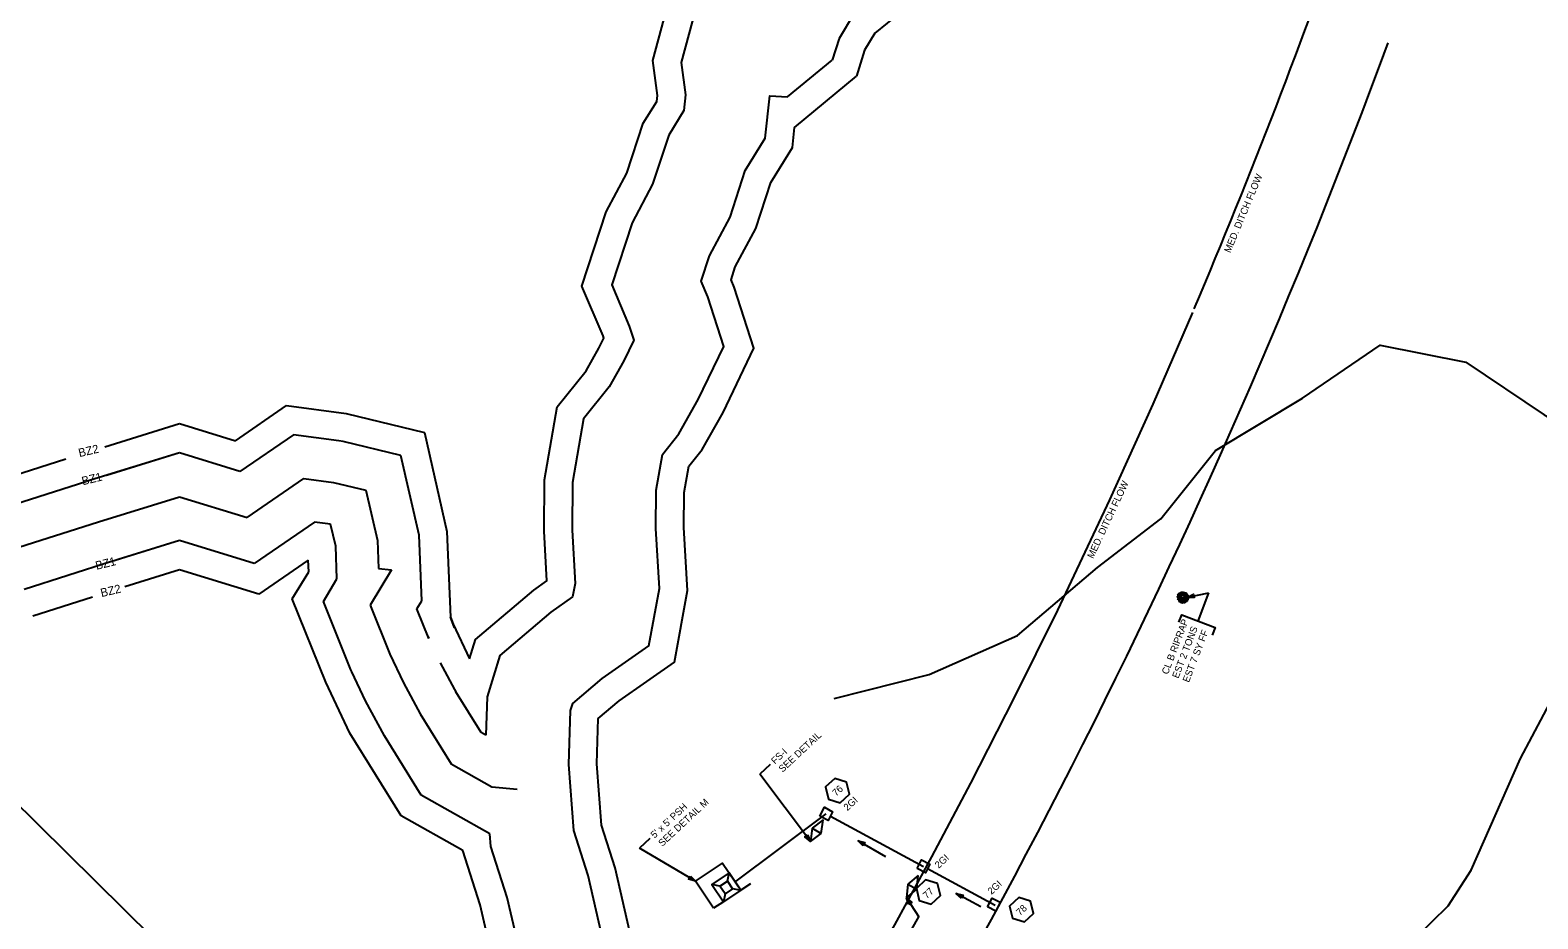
# Model space of a CAD drawing. Extents: x 2384780 to 2405432, y 547869 to 573706.
# Drawn here: x 2399231 to 2400310, y 561684 to 562319 of the extents above; entities that cross this region are included whole.
import ezdxf

# ---------------------------------------------------------------- set-up
doc = ezdxf.new("R2010")
doc.units = 0
for name, color, linetype in [('Default', 7, 'Continuous'), ('Old_Level_1', 7, 'Continuous'), ('Old_Level_19', 7, 'Continuous'), ('Old_Level_20', 7, 'Continuous'), ('Old_Level_5', 7, 'Continuous'), ('Old_Level_6', 7, 'Continuous'), ('Old_Level_62', 7, 'Continuous'), ('Old_Level_63', 7, 'Continuous'), ('Old_Level_9', 7, 'Continuous'), ('Prop Buffer Zone 1', 7, 'Continuous'), ('Prop Buffer Zone 2', 7, 'Continuous'), ('Prop Drainage Box Number Symbol CELL', 7, 'Continuous')]:
    doc.layers.add(name, color=color, linetype=linetype)

msp = doc.modelspace()

# ---------------------------------------------------------------- linework, layer by layer
at = {"layer": 'Default'}
msp.add_arc((2395689.3, 563976), 4811, 326.2779, 339.7425, dxfattribs=at)
at = {"layer": 'Old_Level_1'}
for p, q in [((2399760.5, 561794.1), (2399753.1, 561787.2)), ((2399789.3, 561739), (2399753.1, 561787.2)), ((2399735.2, 561709.8), (2399800.5, 561758.9)), ((2399803.6, 561757.2), (2399870.2, 561721.1)), ((2399674.3, 561741.1), (2399667, 561734.3)), ((2399707.1, 561710.7), (2399667, 561734.3)), ((2399730, 561710.7), (2399731.2, 561716.5)), ((2399873.2, 561719.6), (2399921.5, 561693.5)), ((2399724.5, 561707.1), (2399718.8, 561708.3)), ((2399728.2, 561701.6), (2399727, 561695.9)), ((2399733.6, 561705.3), (2399739.4, 561704.1)), ((2399746.4, 561708.7), (2399739.4, 561704.1)), ((2399858, 561698.8), (2399866.9, 561685)), ((2399727, 561695.9), (2399720, 561691.2)), ((2399861.9, 561676.4), (2399866.9, 561685))]:
    msp.add_line(p, q, dxfattribs=at)
for points in [[(2399796, 561757.2), (2399799.3, 561763.5), (2399805.2, 561760.3), (2399802, 561754.1)], [(2399787.3, 561743.8), (2399789.3, 561739), (2399785.3, 561742.3)], [(2399703.4, 561714.2), (2399707.1, 561710.7), (2399702.1, 561712.1)], [(2399728.2, 561701.6), (2399724.5, 561707.1), (2399730, 561710.7), (2399733.6, 561705.2)], [(2399859.7, 561693.9), (2399858, 561698.8), (2399861.8, 561695.3)]]:
    msp.add_lwpolyline(points, close=True, dxfattribs=at)
for points in [[(2399720, 561691.2), (2399707.1, 561710.7), (2399726.5, 561723.5), (2399739.4, 561704.1)], [(2399739.4, 561704.1), (2399731.2, 561716.5), (2399718.8, 561708.3), (2399727, 561695.9)], [(2399739.4, 561704.1), (2399727, 561695.9)]]:
    msp.add_lwpolyline(points, dxfattribs=at)
for centre, radius in [((2400052.3, 561914.1), 0.298), ((2400052.7, 561915.6), 0.385), ((2400052.8, 561914.7), 0.385), ((2400053.9, 561913.9), 0.854), ((2400053.4, 561916.3), 0.385), ((2400053.6, 561915.5), 0.385), ((2400054.3, 561916.8), 0.385), ((2400054.6, 561915.2), 0.55), ((2400054.7, 561916.1), 0.298), ((2400055.3, 561916.9), 0.55), ((2400055.9, 561914.1), 1.02), ((2400055.5, 561915.7), 0.4), ((2400056.2, 561916.3), 0.298), ((2400056.3, 561917), 0.298), ((2400056.4, 561915.6), 0.298), ((2400057.1, 561916.6), 0.55), ((2400057.3, 561915.4), 0.55), ((2400057.7, 561914.1), 0.718), ((2400058.1, 561916.4), 0.385), ((2400058.5, 561915.4), 0.55), ((2400059.3, 561914.7), 0.385), ((2400052.6, 561913.4), 0.298), ((2400052.8, 561912.5), 0.55), ((2400053.5, 561911.7), 0.298), ((2400053.8, 561910.9), 0.55), ((2400053.8, 561912.6), 0.298), ((2400054.2, 561912), 0.298), ((2400054.8, 561912.7), 0.55), ((2400054.7, 561910.2), 0.385), ((2400055, 561911.2), 0.55), ((2400055.7, 561910), 0.55), ((2400056.1, 561912.2), 0.718), ((2400056.2, 561910.9), 0.298), ((2400057, 561910.3), 0.55), ((2400057.4, 561912.7), 0.55), ((2400057.5, 561911.6), 0.55), ((2400057.8, 561910.7), 0.298), ((2400058.6, 561911.2), 0.55), ((2400058.4, 561913.2), 0.298), ((2400058.4, 561912.5), 0.298), ((2400058.8, 561914), 0.298), ((2400059, 561912.1), 0.385), ((2400059.3, 561913.2), 0.55)]:
    msp.add_circle(centre, radius, dxfattribs=at)
at = {"layer": 'Old_Level_19'}
for points in [[(2400062.7, 562117.3), (2400034.3, 562051.9), (2400003.4, 561983.5), (2399966, 561904.4), (2399935.2, 561841.9)], [(2399935.2, 561841.9), (2399903.8, 561780.7), (2399876, 561728.1), (2399849.4, 561679.3), (2399802.5, 561596.2), (2399773.7, 561547.1), (2399724, 561465.4), (2399672.9, 561385.1), (2399604.3, 561282.6), (2399518.3, 561161.7)]]:
    msp.add_lwpolyline(points, dxfattribs=at)
msp.add_arc((2395691.9, 563975.6), 4749.5, 337.002, 344.5278, dxfattribs=at)
at = {"layer": 'Old_Level_20'}
for p in [(2400059.4, 561913.8), (2400066.7, 561896.7)]:
    msp.add_line(p, (2400074.5, 561916.9), dxfattribs=at)
msp.add_lwpolyline([(2400064, 561913.4), (2400058.9, 561913.5), (2400063.4, 561915.9)], close=True, dxfattribs=at)
msp.add_lwpolyline([(2400053, 561895.8), (2400055, 561901.2), (2400078.9, 561892), (2400076.8, 561886.7)], dxfattribs=at)
at = {"layer": 'Old_Level_5'}
for p, q in [((2399843.3, 561728), (2399823.4, 561739.6)), ((2399911.2, 561692.2), (2399893.7, 561701.9))]:
    msp.add_line(p, q, dxfattribs=at)
for points in [[(2399827.1, 561736), (2399823.4, 561739.6), (2399828.3, 561738.2)], [(2399897.5, 561698.4), (2399893.7, 561701.9), (2399898.7, 561700.6)]]:
    msp.add_lwpolyline(points, close=True, dxfattribs=at)
at = {"layer": 'Old_Level_6'}
for p, q in [((2399386.2, 561970.8), (2399426.9, 561998.7)), ((2399426.9, 561998.7), (2399448, 561995.9)), ((2399448, 561995.9), (2399471.2, 561990.3)), ((2399471.2, 561990.3), (2399479.5, 561954.2)), ((2399279.9, 561967.7), (2399337.8, 561985.6)), ((2399337.8, 561985.6), (2399386.2, 561970.8)), ((2399217.7, 561947.8), (2399279.9, 561967.7)), ((2399479.5, 561954.2), (2399480.3, 561934.2)), ((2399489.5, 561933.3), (2399474.2, 561908.1)), ((2399480.3, 561934.2), (2399489.5, 561933.3)), ((2399474.2, 561908.1), (2399488.4, 561873.1)), ((2399488.4, 561873.1), (2399498.1, 561852.4)), ((2399498.1, 561852.4), (2399510.1, 561830.3)), ((2399510.1, 561830.3), (2399532.2, 561794.6)), ((2399532.2, 561794.6), (2399561.3, 561778.2)), ((2399561.3, 561778.2), (2399579.4, 561776.4))]:
    msp.add_line(p, q, dxfattribs=at)
at = {"layer": 'Old_Level_62'}
for points in [[(2399821.1, 561435.1), (2399926.6, 561478.8), (2399983.8, 561509.2), (2400100, 561551), (2400122.9, 561580.9), (2400187.2, 561635.8), (2400245.6, 561693), (2400262.2, 561718.5), (2400297.4, 561798.3), (2400322.4, 561845.6), (2400375.3, 561929.9), (2400350.2, 561971.4), (2400342.7, 562028.9), (2400380.5, 562062.2), (2400432.1, 562042.4), (2400480, 562001.2), (2400538.6, 562017.4), (2400592.9, 562087.6), (2400691.4, 562124.8), (2400752.6, 562153.7), (2400786.1, 562181.7), (2400835.1, 562178.9), (2400922.9, 562247.5), (2401014.1, 562330.8)], [(2399806.2, 561841.2), (2399874.3, 561858.4), (2399937.4, 561886.4), (2399994.7, 561935), (2400040, 561969.9), (2400079.2, 562018.6), (2400141.4, 562056.1), (2400196.9, 562094), (2400258.3, 562081.8), (2400314.4, 562044.3), (2400342.7, 562028.9)]]:
    msp.add_lwpolyline(points, dxfattribs=at)
at = {"layer": 'Old_Level_63'}
msp.add_lwpolyline([(2399645.6, 561347.3), (2398726.2, 562255.3), (2398336.6, 562216.2)], dxfattribs=at)
at = {"layer": 'Old_Level_9'}
for p, q in [((2399798.5, 561754.4), (2399790.6, 561748.6)), ((2399797, 561744.8), (2399798.5, 561754.4)), ((2399790.6, 561748.6), (2399789.3, 561739)), ((2399789.3, 561739), (2399797, 561744.8)), ((2399790.6, 561748.6), (2399797, 561744.8)), ((2399866.5, 561714.6), (2399858.9, 561708.4)), ((2399865.4, 561704.9), (2399866.5, 561714.6)), ((2399858.9, 561708.4), (2399858, 561698.8)), ((2399858, 561698.8), (2399865.4, 561704.9)), ((2399858.9, 561708.4), (2399865.4, 561704.9))]:
    msp.add_line(p, q, dxfattribs=at)
for points in [[(2399865.6, 561719.6), (2399868.8, 561725.8), (2399874.8, 561722.7), (2399871.6, 561716.5)], [(2399916, 561692.3), (2399919.3, 561698.5), (2399925.2, 561695.5), (2399922, 561689.2)]]:
    msp.add_lwpolyline(points, close=True, dxfattribs=at)
at = {"layer": 'Prop Buffer Zone 1'}
for p, q in [((2399419.4, 562030), (2399381.1, 562003.7)), ((2399451.9, 562025.7), (2399419.4, 562030)), ((2399455, 562025.1), (2399451.9, 562025.7)), ((2399496.3, 562015.1), (2399455, 562025.1)), ((2399496.3, 562015.1), (2399455, 562025.1)), ((2399337.8, 562017), (2399271.1, 561996.4)), ((2399337.8, 562017), (2399285.6, 562000.9)), ((2399381.1, 562003.7), (2399337.8, 562017)), ((2399509.3, 561958.2), (2399496.3, 562015.1)), ((2399509.3, 561958.2), (2399496.3, 562015.1)), ((2399270.8, 561996.3), (2399208.6, 561976.4)), ((2399434.4, 561967.5), (2399391.3, 561937.9)), ((2399434.4, 561967.5), (2399391.3, 561937.9)), ((2399446, 561965.9), (2399434.4, 561967.5)), ((2399446, 561965.9), (2399434.4, 561967.5)), ((2399449.6, 561950.2), (2399446, 561965.9)), ((2399449.6, 561950.2), (2399446, 561965.9)), ((2399511.2, 561911.1), (2399509.3, 561958.2)), ((2399511.2, 561911.1), (2399509.3, 561958.2)), ((2399337.9, 561954.2), (2399288.8, 561939.1)), ((2399337.9, 561954.2), (2399294, 561940.7)), ((2399391.3, 561937.9), (2399337.9, 561954.2)), ((2399391.3, 561937.9), (2399337.9, 561954.2)), ((2399450.5, 561926.8), (2399449.6, 561950.2)), ((2399450.5, 561926.8), (2399449.6, 561950.2)), ((2399289.1, 561939.2), (2399226.8, 561919.3)), ((2399440.8, 561910.7), (2399450.5, 561926.8)), ((2399440.8, 561910.7), (2399450.5, 561926.8)), ((2399460.5, 561861.9), (2399440.8, 561910.7)), ((2399460.5, 561861.9), (2399440.8, 561910.7)), ((2399507.7, 561905.4), (2399511.2, 561911.1)), ((2399507.7, 561905.4), (2399511.2, 561911.1)), ((2399516.2, 561884.3), (2399507.7, 561905.4)), ((2399516.2, 561884.3), (2399507.7, 561905.4)), ((2399461.2, 561860.3), (2399460.5, 561861.9)), ((2399536.5, 561844.6), (2399524.5, 561866.7)), ((2399471, 561839.6), (2399461.2, 561860.3)), ((2399484.6, 561814.5), (2399471, 561839.6)), ((2399553.6, 561816.9), (2399535.6, 561846.1)), ((2399553.6, 561816.9), (2399535.6, 561846.1)), ((2399510.7, 561772.2), (2399484.6, 561814.5)), ((2399557.1, 561815), (2399553.6, 561816.9)), ((2399557.1, 561815), (2399553.6, 561816.9)), ((2399560, 561744.5), (2399510.7, 561772.2))]:
    msp.add_line(p, q, dxfattribs=at)
for points in [[(2400012, 562540.3), (2399997.4, 562496.9), (2399961.5, 562460.1), (2399923.6, 562417.6), (2399894.5, 562392.2), (2399867.5, 562366.1), (2399840.9, 562347.5), (2399820.2, 562330.5), (2399809.8, 562313.5), (2399804.9, 562298)], [(2399753.1, 562333.2), (2399707.7, 562336.7), (2399696.9, 562296.3), (2399699.9, 562273), (2399698.7, 562261.8), (2399687.9, 562244.3), (2399676.4, 562209.1), (2399661.7, 562181.5), (2399647.1, 562137.2), (2399659.7, 562107.6), (2399662.9, 562097.6), (2399655.8, 562082.8), (2399645.4, 562064.3), (2399627, 562041.4), (2399619.1, 561995.8), (2399618.8, 561961.6), (2399620.9, 561923.6), (2399619.1, 561914), (2399603.5, 561903.1), (2399567, 561872.1), (2399558, 561842.6), (2399557.1, 561815)], [(2399772.8, 562271.6), (2399804.9, 562298)], [(2399627.4, 561613.2), (2399639.8, 561673), (2399630.2, 561714.8), (2399620, 561746.9), (2399616.4, 561794.2), (2399617.7, 561832.7), (2399619.2, 561837.7), (2399640.2, 561855.5), (2399673.8, 561879), (2399681.2, 561919.9), (2399678.8, 561963), (2399679, 561990.4), (2399683.4, 562015.9), (2399695.2, 562030.6), (2399709.1, 562055.1), (2399727.3, 562093.2), (2399716, 562128.6), (2399711.2, 562139.9), (2399717.1, 562157.9), (2399731.8, 562185.5), (2399742.7, 562218.9), (2399757, 562242), (2399760.2, 562272.5), (2399772.8, 562271.6)], [(2399577, 561665.6), (2399578.4, 561672.4), (2399572.3, 561698.9), (2399560.7, 561735.4), (2399560, 561744.5)]]:
    msp.add_lwpolyline(points, dxfattribs=at)
at = {"layer": 'Prop Buffer Zone 2'}
for p, q in [((2399377.8, 562025.6), (2399414.4, 562050.8)), ((2399414.4, 562050.8), (2399457.2, 562045.1)), ((2399457.2, 562045.1), (2399513.1, 562031.6)), ((2399284.4, 562021.4), (2399337.8, 562037.9)), ((2399337.8, 562037.9), (2399377.8, 562025.6)), ((2399513.1, 562031.6), (2399529.2, 561960.8)), ((2399202.5, 561995.5), (2399256.6, 562012.8)), ((2399529.2, 561960.8), (2399531.7, 561899.4)), ((2399430, 561940.2), (2399394.7, 561915.9)), ((2399430.3, 561932), (2399430, 561940.2)), ((2399337.9, 561933.3), (2399298.8, 561921.2)), ((2399394.7, 561915.9), (2399337.9, 561933.3)), ((2399418.5, 561912.5), (2399430.3, 561932)), ((2399275.5, 561913.8), (2399232.9, 561900.2)), ((2399442.5, 561853), (2399418.5, 561912.5)), ((2399534.7, 561891.8), (2399531.7, 561899.4)), ((2399531.7, 561899.4), (2399533.6, 561894.5)), ((2399533.6, 561894.5), (2399545.3, 561869.6)), ((2399515.5, 561885.9), (2399516.2, 561884.3)), ((2399459.8, 561816.6), (2399442.5, 561853)), ((2399496.4, 561757.3), (2399459.8, 561816.6)), ((2399540.6, 561732.5), (2399496.4, 561757.3))]:
    msp.add_line(p, q, dxfattribs=at)
for points in [[(2400028.2, 562525.6), (2400014.9, 562486.2), (2399976.2, 562446.4), (2399937.7, 562403.3), (2399908, 562377.4), (2399880.2, 562350.6), (2399853, 562331.6), (2399835.5, 562317.2), (2399828.1, 562305.1), (2399822.2, 562286.4)], [(2399545.3, 561869.6), (2399549.6, 561883.6), (2399591.3, 561918.9), (2399600.8, 561925.5), (2399598.8, 561961.1), (2399599.1, 561997.6), (2399608.1, 562049.9), (2399628.8, 562075.6), (2399638, 562092), (2399641.4, 562099.1), (2399640.9, 562100.7), (2399625.8, 562136.3), (2399643.2, 562189.4), (2399657.9, 562217), (2399669.7, 562252.8), (2399679.3, 562268.4), (2399679.8, 562272.7), (2399676.6, 562297.7), (2399692.7, 562357.9), (2399740.9, 562354.2)], [(2399652, 561612.4), (2399660.3, 561673.3), (2399649.5, 561720.1), (2399639.7, 561750.8), (2399636.4, 561794.6), (2399637.5, 561827), (2399652.4, 561839.6), (2399692, 561867.3), (2399701.3, 561918.6), (2399698.8, 561963.5), (2399699, 561988.6), (2399702.2, 562007.4), (2399711.9, 562019.3), (2399726.8, 562045.9), (2399748.7, 562091.8), (2399734.7, 562135.5), (2399732.5, 562140.8), (2399735.5, 562150), (2399750.2, 562177.6), (2399761, 562210.4), (2399776.4, 562235.4), (2399777.9, 562249.8), (2399822.2, 562286.4)], [(2399558, 561672), (2399553, 561693.6), (2399540.6, 561732.5)]]:
    msp.add_lwpolyline(points, dxfattribs=at)
at = {"layer": 'Prop Drainage Box Number Symbol CELL'}
for points in [[(2399815.2, 561781.5), (2399806.7, 561784.1), (2399800.1, 561778), (2399802.2, 561769.3), (2399810.7, 561766.7), (2399817.3, 561772.8)], [(2399880.3, 561709), (2399871.7, 561711.6), (2399865.2, 561705.5), (2399867.2, 561696.8), (2399875.7, 561694.2), (2399882.3, 561700.3)], [(2399946.9, 561696.3), (2399938.4, 561698.9), (2399931.8, 561692.8), (2399933.8, 561684.1), (2399942.4, 561681.5), (2399948.9, 561687.6)]]:
    msp.add_lwpolyline(points, close=True, dxfattribs=at)

# ---------------------------------------------------------------- texts
at = {"layer": 'Old_Level_1'}
for s, rotation, p in [('CL B RIPRAP', 68.9999, (2400045.1, 561858.1)), ('EST 2 TONS', 68.9999, (2400052.6, 561855.3)), ('EST 7 SY FF', 68.9999, (2400060.1, 561852.4)), ('SEE DETAIL', 43, (2399769.4, 561788.1)), ('FS-I', 43, (2399764, 561793.9)), ("5' x 5' PSH", 43, (2399677.8, 561741)), ('SEE DETAIL M', 43, (2399683.3, 561735.1)), ('2GI', 43, (2399815.8, 561760.6))]:
    msp.add_text(s, height=5, rotation=rotation, dxfattribs=at).set_placement(p)
at = {"layer": 'Old_Level_19'}
for rotation, p in [(67.3015, (2400089.7, 562159.7)), (64.8822, (2399991.6, 561941))]:
    msp.add_text('MED. DITCH FLOW', height=5, rotation=rotation, dxfattribs=at).set_placement(p)
at = {"layer": 'Old_Level_5'}
for p in [(2399881.1, 561719.4), (2399918.9, 561700.7)]:
    msp.add_text('2GI', height=5, rotation=43, dxfattribs=at).set_placement(p)
at = {"layer": 'Prop Buffer Zone 1'}
for p in [(2399268.7, 561993.8), (2399278.5, 561933.3)]:
    msp.add_text('BZ1', height=6, rotation=13.8534, dxfattribs=at).set_placement(p)
at = {"layer": 'Prop Buffer Zone 2'}
for p in [(2399266.3, 562013.9), (2399282.1, 561913.8)]:
    msp.add_text('BZ2', height=6, rotation=13.336, dxfattribs=at).set_placement(p)
at = {"layer": 'Prop Drainage Box Number Symbol CELL'}
for s, p in [('76', (2399807.7, 561771)), ('77', (2399872.6, 561697.7)), ('78', (2399939.3, 561685.6))]:
    msp.add_text(s, height=5, rotation=43, dxfattribs=at).set_placement(p)

doc.saveas('drawing.dxf')
